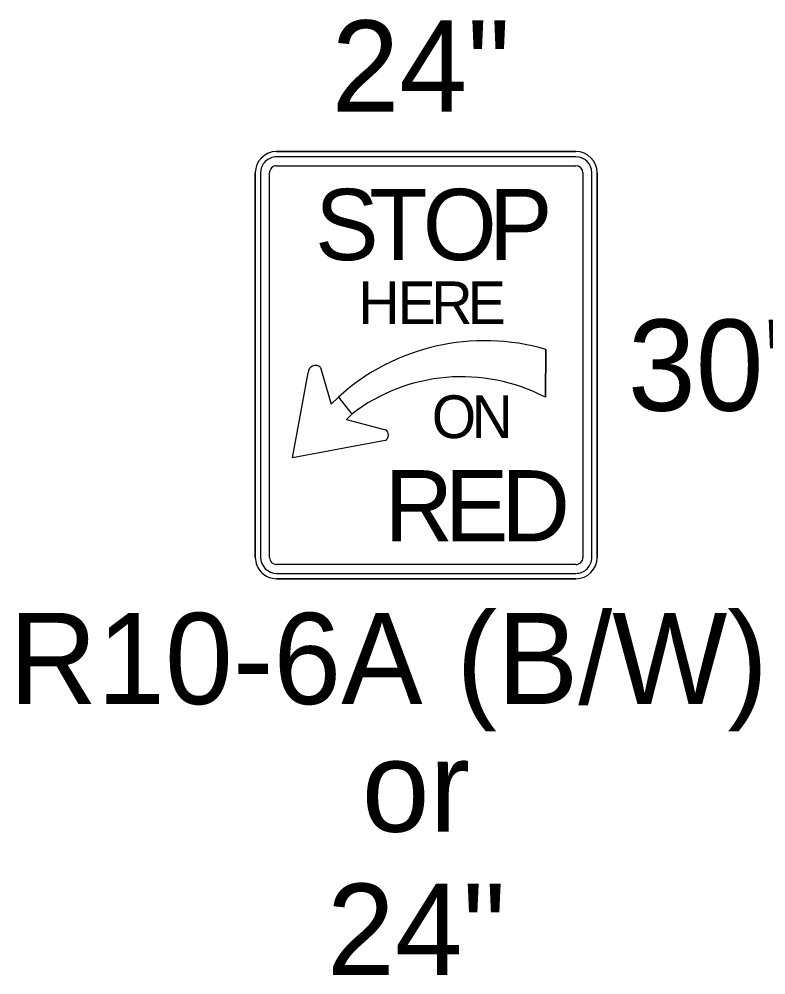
# Model space of a CAD drawing. Extents: x 99999.1 to 100095.7, y 99995 to 100010.7.
# Drawn here: x 100043.919 to 100044.575, y 100004.615 to 100005.454 of the extents above; entities that cross this region are included whole.
import ezdxf

# ---------------------------------------------------------------- set-up
doc = ezdxf.new("R2010")
doc.units = 0
doc.layers.add('TR_SN_ConstructionSigns', color=7, linetype='Continuous')

msp = doc.modelspace()

# ---------------------------------------------------------------- linework, layer by layer
at = {"layer": 'TR_SN_ConstructionSigns'}
for p, q in [((100044.4079, 100005.33733), (100044.1454, 100005.33733)), ((100044.1454, 100005.33733), (100044.4079, 100005.33733)), ((100044.4079, 100005.33733), (100044.1454, 100005.33733)), ((100044.1454, 100005.33733), (100044.4079, 100005.33733)), ((100044.4079, 100005.33264), (100044.1454, 100005.33264)), ((100044.1454, 100005.32483), (100044.4079, 100005.32483)), ((100044.12665, 100005.31858), (100044.12665, 100004.98108)), ((100044.12665, 100004.98108), (100044.12665, 100005.31858)), ((100044.12665, 100005.31858), (100044.12665, 100004.98108)), ((100044.12665, 100004.98108), (100044.12665, 100005.31858)), ((100044.13134, 100005.31858), (100044.13134, 100004.98108)), ((100044.13915, 100004.98108), (100044.13915, 100005.31858)), ((100044.41415, 100005.31858), (100044.41415, 100004.98108)), ((100044.42196, 100004.98108), (100044.42196, 100005.31858)), ((100044.42665, 100004.98108), (100044.42665, 100005.31858)), ((100044.42665, 100005.31858), (100044.42665, 100004.98108)), ((100044.42665, 100004.98108), (100044.42665, 100005.31858)), ((100044.42665, 100005.31858), (100044.42665, 100004.98108)), ((100044.38162, 100005.16355), (100044.38127, 100005.12158)), ((100044.38127, 100005.12158), (100044.38162, 100005.16355)), ((100044.18388, 100005.14785), (100044.19332, 100005.11544)), ((100044.15946, 100005.06858), (100044.17306, 100005.14302)), ((100044.19332, 100005.11544), (100044.19964, 100005.12177)), ((100044.19964, 100005.12177), (100044.21134, 100005.10688)), ((100044.19964, 100005.12177), (100044.21134, 100005.10688)), ((100044.21134, 100005.10688), (100044.20659, 100005.10212)), ((100044.20659, 100005.10212), (100044.24078, 100005.09293)), ((100044.2406, 100005.08365), (100044.15946, 100005.06858)), ((100044.4079, 100004.97483), (100044.1454, 100004.97483)), ((100044.1454, 100004.96702), (100044.4079, 100004.96702)), ((100044.1454, 100004.96233), (100044.4079, 100004.96233)), ((100044.4079, 100004.96233), (100044.1454, 100004.96233)), ((100044.1454, 100004.96233), (100044.4079, 100004.96233)), ((100044.4079, 100004.96233), (100044.1454, 100004.96233))]:
    msp.add_line(p, q, dxfattribs=at)
for centre, radius, start, end in [((100044.1454, 100005.31858), 0.01875, 90, 180), ((100044.1454, 100005.31858), 0.01875, 90, 180), ((100044.1454, 100005.31858), 0.01875, 90, 180), ((100044.1454, 100005.31858), 0.01875, 90, 180), ((100044.1454, 100005.31858), 0.01406, 90, 180.00001), ((100044.4079, 100005.31858), 0.01875, 0, 90), ((100044.4079, 100005.31858), 0.01875, 0, 90), ((100044.4079, 100005.31858), 0.01875, 0, 90), ((100044.4079, 100005.31858), 0.01875, 0, 90), ((100044.4079, 100005.31858), 0.01406, 0, 90), ((100044.1454, 100005.31858), 0.00625, 90, 180.00001), ((100044.4079, 100005.31858), 0.00625, 0, 90), ((100044.32787, 100004.98042), 0.19085, 73.6434, 132.21315), ((100044.32787, 100004.98042), 0.19085, 73.6434, 132.21315), ((100044.30783, 100004.98102), 0.15859, 62.4149, 127.4769), ((100044.30783, 100004.98102), 0.15859, 62.4149, 127.4769), ((100044.1454, 100004.98108), 0.01875, 180, 270.00001), ((100044.1454, 100004.98108), 0.01875, 180, 270.00001), ((100044.1454, 100004.98108), 0.01875, 180, 270.00001), ((100044.1454, 100004.98108), 0.01875, 180, 270.00001), ((100044.1454, 100004.98108), 0.01406, 180.00001, 270), ((100044.1454, 100004.98108), 0.00625, 180.00001, 270), ((100044.4079, 100004.98108), 0.01875, 270.00001, 0.00001), ((100044.4079, 100004.98108), 0.01875, 270.00001, 0.00001), ((100044.4079, 100004.98108), 0.01875, 270.00001, 0.00001), ((100044.4079, 100004.98108), 0.01406, 270, 0.00001), ((100044.4079, 100004.98108), 0.00625, 270, 0.00001), ((100044.4079, 100004.98108), 0.01875, 270.00001, 0.00001)]:
    msp.add_arc(centre, radius, start, end, dxfattribs=at)
for centre, major_axis, ratio, start_param, end_param in [((100044.17953, 100005.1431), (-0.00647, -0.00009), 0.989437, 3.962549, 6.283185), ((100044.23839, 100005.08834), (-0.0046, 0.00239), 0.999053, 2.490568, 4.712389)]:
    msp.add_ellipse(centre, major_axis=major_axis, ratio=ratio, start_param=start_param, end_param=end_param, dxfattribs=at)

# ---------------------------------------------------------------- texts
for s, p in [('24"', (100044.19357, 100005.37233)), ('30"', (100044.45358, 100005.10983)), ('R10-6A (B/W)', (100043.91069, 100004.85233)), ('or', (100044.22007, 100004.74033)), ('24"', (100044.18952, 100004.61461))]:
    msp.add_text(s, height=0.08, rotation=360, dxfattribs=at).set_placement(p)
for s, height, p in [('S', 0.0625, (100044.17915, 100005.24202)), ('T', 0.0625, (100044.22665, 100005.24202)), ('O', 0.0625, (100044.27353, 100005.24202)), ('P', 0.0625, (100044.33165, 100005.24202)), ('H', 0.0375, (100044.21703, 100005.18577)), ('E', 0.0375, (100044.25153, 100005.18577)), ('R', 0.0375, (100044.28115, 100005.18577)), ('E', 0.0375, (100044.31303, 100005.18577)), ('O', 0.0375, (100044.28152, 100005.08577)), ('N', 0.0375, (100044.3164, 100005.08577)), ('R', 0.0625, (100044.23992, 100004.99514)), ('E', 0.0625, (100044.29305, 100004.99514)), ('D', 0.0625, (100044.34242, 100004.99514))]:
    msp.add_text(s, height=height, dxfattribs=at).set_placement(p)

doc.saveas('drawing.dxf')
